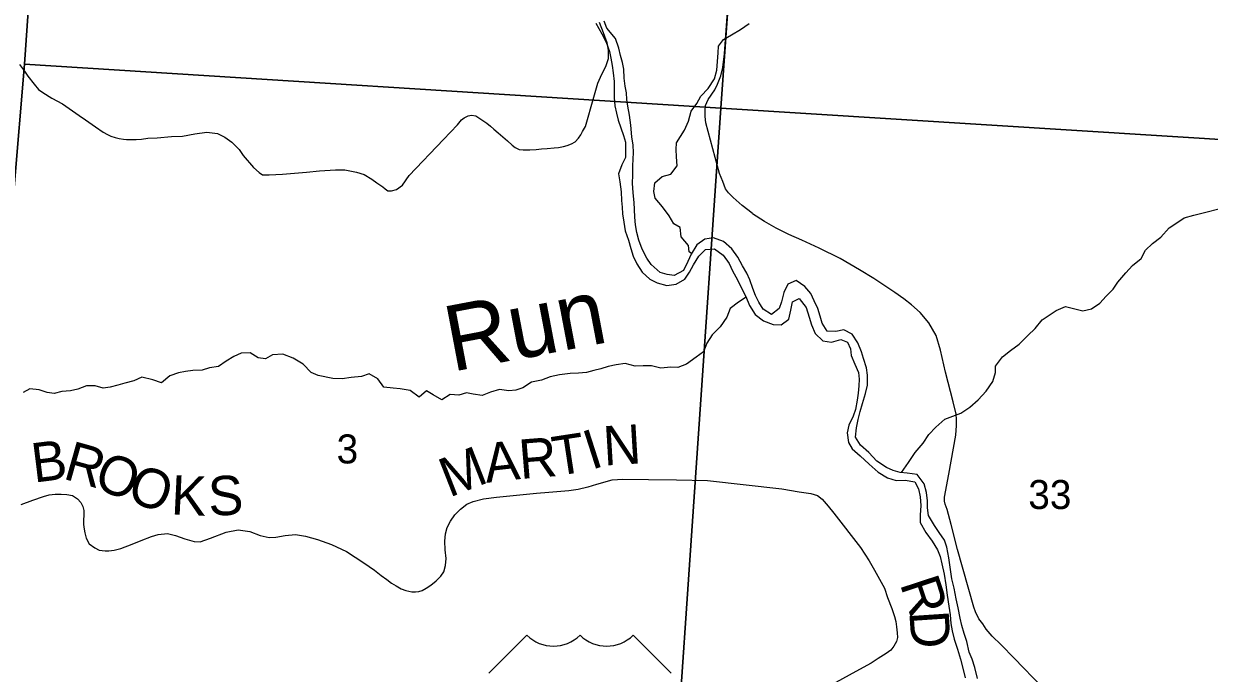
# Model space of a CAD drawing. Extents: x -8.2 to 34, y 0 to 22.
# Drawn here: x 3.458 to 5.17, y 17.933 to 18.871 of the extents above; entities that cross this region are included whole.
import ezdxf

# ---------------------------------------------------------------- set-up
doc = ezdxf.new("R2010")
doc.units = 0
for name, color, linetype in [('GM_X_Corporation', 7, 'Continuous'), ('GM_X_County_Road', 7, 'Continuous'), ('GM_X_County_Road_Text', 7, 'Continuous'), ('GM_X_Major_River', 7, 'Continuous'), ('GM_X_Minor_River', 7, 'Continuous'), ('GM_X_Minor_River_Text', 7, 'Continuous'), ('GM_X_Section_Text', 7, 'Continuous'), ('GM_X_State_Route', 7, 'Continuous'), ('GM_X_Township_Road', 7, 'Continuous'), ('GM_X_US_Shield', 7, 'Continuous')]:
    doc.layers.add(name, color=color, linetype=linetype)

msp = doc.modelspace()

# ---------------------------------------------------------------- linework, layer by layer
at = {"layer": 'GM_X_Corporation'}
for points in [[(3.5308, 19.8461), (4.5379, 19.7849), (4.465, 18.749), (3.459, 18.8121), (3.474, 19.0276), (3.5026, 19.4408)], [(4.5379, 19.7849), (5.5693, 19.7272), (5.5363, 19.3151), (5.5032, 18.9017), (5.4857, 18.6849), (4.465, 18.749)], [(2.4767, 19.0935), (3.474, 19.0276), (3.459, 18.8121), (3.4438, 18.6343), (2.9025, 18.6602), (2.4436, 18.691), (2.4444, 18.7015), (2.4582, 18.8825)], [(4.465, 18.749), (4.3947, 17.7241), (3.3856, 17.7912), (3.4438, 18.6343), (3.459, 18.8121)], [(5.4857, 18.6849), (5.4744, 18.5035), (5.4208, 17.6558), (4.3947, 17.7241), (4.465, 18.749)]]:
    msp.add_lwpolyline(points, close=True, dxfattribs=at)
at = {"layer": 'GM_X_County_Road'}
for points in [[(4.2734, 18.202), (4.2856, 18.2057), (4.3077, 18.212), (4.3232, 18.213), (4.3605, 18.2122), (4.401, 18.212), (4.4457, 18.2108), (4.5528, 18.1989), (4.5782, 18.1946), (4.5947, 18.1923), (4.6046, 18.1891), (4.6111, 18.1842), (4.6197, 18.1741), (4.6279, 18.1639), (4.6664, 18.1141), (4.6791, 18.0947), (4.6869, 18.0814), (4.7012, 18.0554), (4.7057, 18.0421), (4.7121, 18.0261), (4.7157, 18.0146), (4.7176, 18.0073), (4.7186, 17.9997), (4.7194, 17.9911), (4.72, 17.9841), (4.7184, 17.9784), (4.7147, 17.9718), (4.7102, 17.9657), (4.7035, 17.961), (4.6922, 17.9538), (4.682, 17.9473), (4.6598, 17.935), (4.6119, 17.9088)], [(3.4542, 18.1762), (3.471, 18.1827), (3.4862, 18.1878), (3.4946, 18.1901), (3.5034, 18.1913), (3.512, 18.1913), (3.5199, 18.1909), (3.5285, 18.1891), (3.5355, 18.1846), (3.5404, 18.1792), (3.5433, 18.1733), (3.5447, 18.1678), (3.5447, 18.1606), (3.5443, 18.1541), (3.5443, 18.1473), (3.5449, 18.1409), (3.546, 18.1354), (3.548, 18.1276), (3.5525, 18.1197), (3.5604, 18.1139), (3.5668, 18.1105), (3.5757, 18.1092), (3.5809, 18.1094), (3.5886, 18.1102), (3.5981, 18.1127), (3.6146, 18.1188), (3.6275, 18.1242), (3.6423, 18.1301), (3.6521, 18.133), (3.6656, 18.1346), (3.6771, 18.1315), (3.6906, 18.1268), (3.7039, 18.1227), (3.7127, 18.1223), (3.7277, 18.1276), (3.7502, 18.1362), (3.7674, 18.1395), (3.7844, 18.1371), (3.7993, 18.1313), (3.8124, 18.1287), (3.822, 18.1291), (3.8356, 18.1315), (3.8505, 18.1332), (3.8648, 18.1307), (3.8822, 18.1258), (3.9023, 18.1186), (3.9242, 18.1082), (3.9492, 18.092), (3.9645, 18.0814), (3.9744, 18.0738), (3.9822, 18.0679), (3.9893, 18.0625), (3.9959, 18.0586), (4.003, 18.0546), (4.0098, 18.0521), (4.0184, 18.05), (4.0237, 18.05), (4.0286, 18.0507), (4.0333, 18.0523), (4.0391, 18.0554), (4.046, 18.0597), (4.0536, 18.066), (4.0603, 18.0728), (4.0645, 18.0789), (4.0673, 18.0881), (4.0681, 18.0984), (4.0665, 18.1109), (4.0659, 18.1233), (4.067, 18.1338), (4.0696, 18.1432), (4.0743, 18.152), (4.0808, 18.1616), (4.0888, 18.1698), (4.098, 18.1766), (4.1072, 18.1805), (4.1218, 18.1846), (4.141, 18.187), (4.1984, 18.1928), (4.2164, 18.1942), (4.2452, 18.1964), (4.2586, 18.1985), (4.2725, 18.2018), (4.2734, 18.202)]]:
    msp.add_lwpolyline(points, dxfattribs=at)
at = {"layer": 'GM_X_Major_River'}
for points in [[(4.3348, 18.7244), (4.333, 18.7388), (4.3303, 18.7517), (4.3292, 18.7612), (4.3284, 18.7707), (4.3265, 18.7806), (4.3254, 18.792), (4.3246, 18.8049), (4.3227, 18.8148), (4.3201, 18.8246), (4.3174, 18.8353), (4.3129, 18.8493), (4.3004, 18.8645), (4.2962, 18.8744)], [(4.2844, 18.8714), (4.2928, 18.8562), (4.2992, 18.844), (4.3038, 18.8307), (4.306, 18.8209), (4.3079, 18.8102), (4.3095, 18.8), (4.3106, 18.7874), (4.3106, 18.7643), (4.3117, 18.7521), (4.314, 18.7415), (4.3163, 18.7312)], [(4.3163, 18.7312), (4.3243, 18.7095), (4.327, 18.6996), (4.3273, 18.6901), (4.3269, 18.6776), (4.322, 18.667), (4.317, 18.6537), (4.3189, 18.6423), (4.3208, 18.6279), (4.3215, 18.6154), (4.3223, 18.6059), (4.323, 18.596), (4.3246, 18.5839), (4.3268, 18.5714), (4.3317, 18.5581), (4.3348, 18.5459), (4.3382, 18.5349), (4.3435, 18.5239), (4.3511, 18.5121), (4.3624, 18.5019), (4.3727, 18.4966), (4.3867, 18.4924), (4.4004, 18.4946), (4.4126, 18.5018), (4.4198, 18.5121), (4.4255, 18.5227), (4.4331, 18.5349), (4.4426, 18.5447), (4.4555, 18.5455), (4.468, 18.5363), (4.4771, 18.5242), (4.4817, 18.5136), (4.4889, 18.5007), (4.4957, 18.487), (4.501, 18.4767), (4.5063, 18.4635), (4.5143, 18.4509), (4.5264, 18.4414), (4.5405, 18.4361), (4.5522, 18.4357), (4.5629, 18.4441), (4.5659, 18.457), (4.5682, 18.4691), (4.5781, 18.474), (4.588, 18.4607), (4.5925, 18.4471), (4.5959, 18.4357), (4.6012, 18.4235), (4.6122, 18.4125), (4.6247, 18.4106), (4.6384, 18.4144), (4.6479, 18.411), (4.6521, 18.4011), (4.6532, 18.3916), (4.6585, 18.3791), (4.6638, 18.3669), (4.6649, 18.3571), (4.6642, 18.3476), (4.6634, 18.337), (4.6619, 18.3271), (4.6596, 18.3134), (4.6561, 18.304), (4.6497, 18.2911), (4.6474, 18.2797), (4.6493, 18.266), (4.6546, 18.2565), (4.666, 18.2466), (4.6789, 18.2345), (4.6921, 18.2231), (4.7054, 18.2147), (4.7183, 18.2109), (4.7312, 18.2113), (4.7449, 18.209), (4.7506, 18.1988), (4.7529, 18.1874), (4.7536, 18.1749), (4.7528, 18.1608), (4.7528, 18.1502), (4.7612, 18.1361), (4.7703, 18.1232), (4.7778, 18.1107), (4.7816, 18.1012), (4.7839, 18.0906), (4.7873, 18.0758), (4.7899, 18.0602), (4.7918, 18.0454), (4.7941, 18.0295), (4.796, 18.0169), (4.7971, 18.0044), (4.799, 17.9938), (4.802, 17.982), (4.8066, 17.9672), (4.8111, 17.9528), (4.8149, 17.938), (4.8179, 17.9258)], [(4.8358, 17.9251), (4.8316, 17.941), (4.8278, 17.9528), (4.8236, 17.963), (4.8202, 17.9782), (4.8165, 17.99), (4.813, 18.0017), (4.8108, 18.012), (4.8078, 18.0272), (4.8047, 18.0401), (4.8021, 18.0556), (4.7987, 18.0689), (4.7964, 18.0826), (4.7942, 18.0993), (4.7911, 18.1149), (4.7881, 18.1247), (4.7801, 18.1357), (4.7733, 18.146), (4.7646, 18.1604), (4.7635, 18.1714), (4.7635, 18.1817), (4.762, 18.1938), (4.7586, 18.2063), (4.7483, 18.2196), (4.7339, 18.2215), (4.7237, 18.2227), (4.7138, 18.2254), (4.7043, 18.2299), (4.6903, 18.2387), (4.6785, 18.2516), (4.6664, 18.2618), (4.6592, 18.2736), (4.6607, 18.2869), (4.6634, 18.299), (4.666, 18.3108), (4.6695, 18.3222), (4.674, 18.3366), (4.6767, 18.3487), (4.6767, 18.3631), (4.6752, 18.3738), (4.671, 18.3874), (4.668, 18.3969), (4.6627, 18.4098), (4.6547, 18.4224), (4.6426, 18.4288), (4.6308, 18.4262), (4.6183, 18.4266), (4.6111, 18.4383), (4.6081, 18.4482), (4.605, 18.4592), (4.5997, 18.4706), (4.5948, 18.4812), (4.5861, 18.4911), (4.5739, 18.4998), (4.5614, 18.4945), (4.5557, 18.4824), (4.5527, 18.4691), (4.5492, 18.4596), (4.5382, 18.4505), (4.5261, 18.4585), (4.5196, 18.4684), (4.5147, 18.4783), (4.5109, 18.4885), (4.5067, 18.5006), (4.5022, 18.5105), (4.4961, 18.5211), (4.4893, 18.5337), (4.4806, 18.5454), (4.4688, 18.5561), (4.4544, 18.5614), (4.4415, 18.5595), (4.4301, 18.5512), (4.4221, 18.5379), (4.4171, 18.5273), (4.4107, 18.5144), (4.3974, 18.5072), (4.3871, 18.5083), (4.3773, 18.5114), (4.364, 18.5228), (4.3579, 18.5322), (4.3511, 18.5452), (4.3466, 18.5581), (4.3435, 18.5691), (4.3416, 18.5801), (4.3405, 18.5915), (4.3401, 18.6025), (4.3398, 18.6123), (4.3383, 18.6264), (4.3371, 18.6404), (4.3375, 18.6522), (4.3379, 18.6655), (4.3383, 18.6753), (4.3387, 18.6848), (4.338, 18.6951), (4.3365, 18.7072), (4.3348, 18.7244)]]:
    msp.add_lwpolyline(points, dxfattribs=at)
at = {"layer": 'GM_X_Minor_River'}
for points in [[(4.4183, 18.73), (4.4221, 18.7446), (4.4304, 18.7557), (4.436, 18.7663), (4.4466, 18.7773), (4.4557, 18.7909), (4.4591, 18.8035), (4.4598, 18.8164), (4.461, 18.8289), (4.4613, 18.8384), (4.4685, 18.8479), (4.4802, 18.8547), (4.4931, 18.8623), (4.5056, 18.871)], [(4.4226, 18.5388), (4.4193, 18.5411), (4.4181, 18.5505), (4.4075, 18.563), (4.4063, 18.5763), (4.3969, 18.5816), (4.39, 18.5933), (4.3805, 18.6062), (4.3699, 18.6187), (4.368, 18.6282), (4.3695, 18.6411), (4.3801, 18.6502), (4.3926, 18.6533), (4.4017, 18.6654), (4.4009, 18.6783), (4.4005, 18.6889), (4.4009, 18.6988), (4.4122, 18.717), (4.4183, 18.73)], [(4.7258, 18.2224), (4.7359, 18.237), (4.7458, 18.2514), (4.7571, 18.2651), (4.7654, 18.2776), (4.7753, 18.2882), (4.7885, 18.2996), (4.7999, 18.3038), (4.8116, 18.308), (4.8245, 18.3168), (4.8366, 18.3274), (4.8483, 18.3399), (4.8578, 18.354), (4.8615, 18.3669), (4.8615, 18.3763), (4.8717, 18.3896), (4.8831, 18.3988), (4.896, 18.4079), (4.9084, 18.4204), (4.9187, 18.4303), (4.9289, 18.4428), (4.9493, 18.4565), (4.9629, 18.4622), (4.9762, 18.4588), (4.9879, 18.4558), (5.0001, 18.4588), (5.0122, 18.4672), (5.0216, 18.4771), (5.0315, 18.4873), (5.0383, 18.4976), (5.05, 18.5109), (5.0595, 18.5215), (5.0719, 18.5314), (5.0784, 18.5435), (5.0882, 18.5534), (5.1003, 18.5625), (5.1124, 18.5758), (5.1234, 18.583), (5.1344, 18.5906), (5.148, 18.5944), (5.1635, 18.5982), (5.1863, 18.604)], [(4.5014, 18.4757), (4.4902, 18.4687), (4.4781, 18.4592), (4.4735, 18.4471), (4.4641, 18.433), (4.4524, 18.4213), (4.4448, 18.4091), (4.4399, 18.3966), (4.4293, 18.389), (4.4153, 18.3791), (4.4028, 18.3742), (4.3926, 18.3745), (4.3782, 18.3734), (4.3649, 18.3768), (4.3528, 18.3768), (4.3411, 18.376), (4.3267, 18.3798), (4.3138, 18.3778), (4.302, 18.3755), (4.2914, 18.3721), (4.2812, 18.3698), (4.271, 18.3672), (4.2592, 18.366), (4.2471, 18.3656), (4.232, 18.3637), (4.2183, 18.3606), (4.2059, 18.3561), (4.1915, 18.353), (4.1786, 18.3446), (4.1687, 18.3416), (4.1585, 18.3404), (4.1453, 18.3423), (4.132, 18.3385), (4.1199, 18.3336), (4.107, 18.3358), (4.0972, 18.3377), (4.0862, 18.3343), (4.0737, 18.3354), (4.0619, 18.3274), (4.0494, 18.3346), (4.0396, 18.3406), (4.029, 18.3315), (4.0161, 18.341), (4.0017, 18.3436), (3.9915, 18.3444), (3.9782, 18.3459), (3.9695, 18.358), (3.9566, 18.3648), (3.9456, 18.3614), (3.9308, 18.3598), (3.9176, 18.3579), (3.9043, 18.3583), (3.8831, 18.3628), (3.8729, 18.3669), (3.8615, 18.3791), (3.8471, 18.3878), (3.8323, 18.3934), (3.8172, 18.3923), (3.8069, 18.3869), (3.7967, 18.3881), (3.785, 18.3956), (3.7717, 18.3949), (3.7615, 18.3903), (3.7501, 18.3831), (3.7391, 18.3758), (3.7263, 18.3735), (3.7157, 18.3701), (3.702, 18.3697), (3.6914, 18.3682), (3.6816, 18.3663), (3.6691, 18.3621), (3.6566, 18.3518), (3.6441, 18.3564), (3.6282, 18.3601), (3.6168, 18.3548), (3.6039, 18.3514), (3.5937, 18.3487), (3.5827, 18.346), (3.5725, 18.3445), (3.5611, 18.3475), (3.5483, 18.3479), (3.5358, 18.3429), (3.5252, 18.3406), (3.513, 18.3395), (3.5017, 18.3368), (3.4918, 18.3383), (3.4801, 18.3417), (3.4668, 18.3432), (3.457, 18.3383)]]:
    msp.add_lwpolyline(points, dxfattribs=at)
at = {"layer": 'GM_X_State_Route'}
msp.add_lwpolyline([(4.9296, 17.9121), (4.8885, 17.9544), (4.8697, 17.9738), (4.857, 17.9863), (4.8483, 17.9961), (4.8434, 18.0041), (4.8377, 18.0111), (4.8329, 18.0214), (4.8303, 18.0279), (4.8067, 18.1115), (4.7974, 18.1476), (4.7919, 18.1689), (4.7891, 18.1768), (4.7879, 18.1812), (4.7881, 18.187), (4.794, 18.2199), (4.8044, 18.2765), (4.8055, 18.2903), (4.8053, 18.2993), (4.8047, 18.3069), (4.8003, 18.3248), (4.7893, 18.3675), (4.7821, 18.3992), (4.776, 18.4206), (4.7651, 18.4389), (4.7527, 18.4538), (4.7402, 18.4648), (4.7291, 18.4734), (4.7161, 18.4827), (4.6857, 18.5025), (4.6652, 18.5153), (4.6372, 18.5317), (4.6067, 18.5464), (4.5817, 18.5579), (4.5632, 18.5664), (4.5446, 18.5753), (4.5277, 18.5851), (4.5107, 18.5962), (4.51, 18.5969), (4.4955, 18.608), (4.4827, 18.6198), (4.4761, 18.6263), (4.4716, 18.6321), (4.4676, 18.6427), (4.4631, 18.6542), (4.4568, 18.6776), (4.4499, 18.7027), (4.4433, 18.7275), (4.4422, 18.7365), (4.4421, 18.7457), (4.4426, 18.7528), (4.4467, 18.7613), (4.4563, 18.7751), (4.4601, 18.7833), (4.4647, 18.7956), (4.4675, 18.8075), (4.4701, 18.827), (4.4757, 18.909)], dxfattribs=at)
at = {"layer": 'GM_X_Township_Road'}
msp.add_lwpolyline([(3.4515, 18.8119), (3.4591, 18.8022), (3.4636, 18.7952), (3.4729, 18.7833), (3.4793, 18.7759), (3.4854, 18.7713), (3.4985, 18.7632), (3.514, 18.755), (3.5377, 18.738), (3.5472, 18.7317), (3.5616, 18.7217), (3.5728, 18.7139), (3.579, 18.7107), (3.5836, 18.7082), (3.59, 18.7065), (3.5959, 18.705), (3.6018, 18.7041), (3.6065, 18.7035), (3.6129, 18.7033), (3.6201, 18.7035), (3.6279, 18.7041), (3.6372, 18.7052), (3.6508, 18.706), (3.6715, 18.7077), (3.6874, 18.7084), (3.705, 18.7115), (3.7225, 18.7141), (3.7376, 18.712), (3.7484, 18.7069), (3.7585, 18.6997), (3.7689, 18.6889), (3.7748, 18.6804), (3.7899, 18.6631), (3.7981, 18.6557), (3.8026, 18.6525), (3.8125, 18.6525), (3.8318, 18.6535), (3.8665, 18.6563), (3.8852, 18.6584), (3.9082, 18.6597), (3.9218, 18.6597), (3.9385, 18.6563), (3.9495, 18.6529), (3.9605, 18.6463), (3.9679, 18.641), (3.9766, 18.6351), (3.9798, 18.6321), (3.9838, 18.6294), (3.9893, 18.6296), (3.9965, 18.6315), (4.0048, 18.6377), (4.0147, 18.6514), (4.0643, 18.7033), (4.0842, 18.7249), (4.0901, 18.7317), (4.0941, 18.7348), (4.0998, 18.7378), (4.1049, 18.7386), (4.1109, 18.7378), (4.1168, 18.734), (4.1212, 18.731), (4.1267, 18.7272), (4.1322, 18.7228), (4.1371, 18.7183), (4.1432, 18.7132), (4.1566, 18.7016), (4.1632, 18.6952), (4.1678, 18.6921), (4.1733, 18.6893), (4.1795, 18.6887), (4.1888, 18.6887), (4.1979, 18.6891), (4.2057, 18.69), (4.2142, 18.6906), (4.2239, 18.6914), (4.2305, 18.6921), (4.2377, 18.6933), (4.243, 18.6946), (4.2491, 18.6974), (4.2546, 18.7001), (4.2591, 18.7052), (4.2625, 18.7101), (4.2652, 18.7149), (4.2692, 18.7223), (4.2813, 18.7647), (4.2871, 18.7849), (4.2908, 18.7933), (4.2993, 18.8106), (4.3027, 18.8204), (4.3025, 18.8324), (4.3006, 18.843), (4.2955, 18.8576), (4.2896, 18.8723)], dxfattribs=at)
at = {"layer": 'GM_X_US_Shield'}
for p, q in [((4.1846, 17.9874), (4.1297, 17.9325)), ((4.3933, 17.9325), (4.3384, 17.9874))]:
    msp.add_line(p, q, dxfattribs=at)
for centre in [(4.223, 18.0267), (4.2999, 18.0267)]:
    msp.add_arc(centre, 0.0549, 225.573, 314.427, dxfattribs=at)

# ---------------------------------------------------------------- texts
at = {"layer": 'GM_X_County_Road_Text'}
for s, rotation, p in [('N', 3.4082, (4.2963, 18.2325)), ('T', 8.6933, (4.2262, 18.2173)), ('I', 17.7957, (4.2778, 18.226)), ('B', 7.0863, (3.4726, 18.2078)), ('R', 344.1913, (3.513, 18.214)), ('M', 21.3961, (4.0725, 18.186)), ('A', 6.3885, (4.1261, 18.2075)), ('R', 4.6457, (4.1753, 18.2131)), ('O', 338.5605, (3.5565, 18.2017)), ('O', 340.1137, (3.6046, 18.1829)), ('K', 357.2828, (3.6698, 18.1622)), ('S', 2.666, (3.7255, 18.1598)), ('R', 288.1708, (4.7232, 18.062)), ('D', 273.8497, (4.737, 18.0213))]:
    msp.add_text(s, height=0.0568, rotation=rotation, dxfattribs=at).set_placement(p)
at = {"layer": 'GM_X_Minor_River_Text'}
msp.add_text('Run', height=0.0947, rotation=10.7508, dxfattribs=at).set_placement((4.0763, 18.3678))
at = {"layer": 'GM_X_Section_Text'}
for s, height, p in [('3', 0.0419, (3.9098, 18.2356)), ('33', 0.04186, (4.909, 18.1698))]:
    msp.add_text(s, height=height, rotation=0, dxfattribs=at).set_placement(p)

doc.saveas('drawing.dxf')
